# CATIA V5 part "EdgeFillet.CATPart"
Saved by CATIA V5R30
Part number: Part1
Bounding box of the stored display mesh (mm): x -55 to 55, y -155 to 25.782, z -44.572 to 40
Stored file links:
  D:\PROJECTS\CATIA V56R 2020\Resources\Parts File\c17_catia_v6_6r2020_prt\EdgeFillet.CATPart
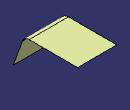
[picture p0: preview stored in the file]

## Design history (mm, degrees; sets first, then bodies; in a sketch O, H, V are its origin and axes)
Body1 (main body)
  Sketch1 on yz-plane, origin (0, 0, 0), H (0, 1, 0), V (0, 0, 1)
    point P1 (25.7818, 40)
    line L1 (25.7818, 40) -> (-124.2182, 40)
    line L2 (-124.2182, 40) -> (-155, -44.5723)
    point P3 (-155, -44.5723)
    length L1 = 150
    length L2 = 90
    angle L2 L1 = 110
    distance P1 H = 40
    distance P3 V = 155
    horizontal: L1 H
  Extrude1: Element1 Sketch1, Lim1 55, Lim2 55
  Fillet1: radius 20, on edge [face of Extrude1 from Sketch1.L1 | face of Extrude1 from Sketch1.L2]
